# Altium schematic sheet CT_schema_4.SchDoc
size 316 x 185 mm
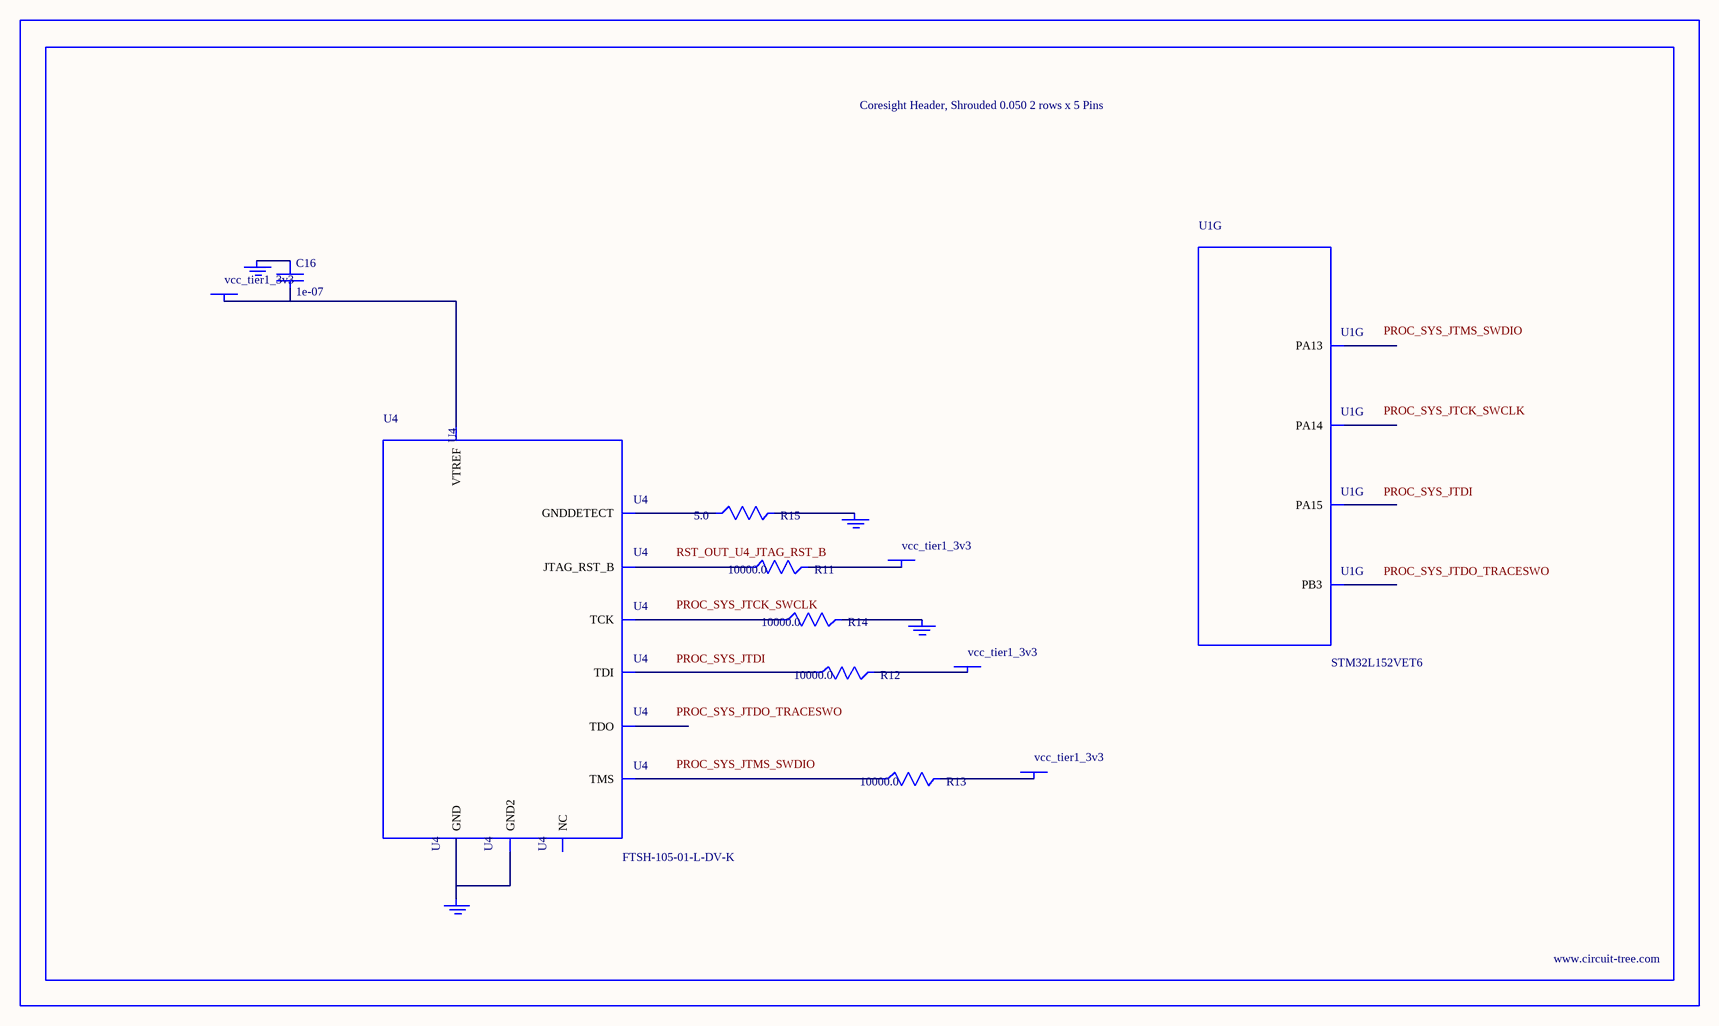
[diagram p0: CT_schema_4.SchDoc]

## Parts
BORDER3  (no value)
C16  1e-07  [C0402]
GND_INSTANCE_3_0  (no value)
GND_INSTANCE_3_1  (no value)
GND_INSTANCE_3_2  (no value)
GND_INSTANCE_3_3  (no value)
POWER_INSTANCE_3_0  vcc_tier1_3v3
POWER_INSTANCE_3_1  vcc_tier1_3v3
POWER_INSTANCE_3_2  vcc_tier1_3v3
POWER_INSTANCE_3_3  vcc_tier1_3v3
R11  10000.0  [R0603]
R12  10000.0  [R0603]
R13  10000.0  [R0603]
R14  10000.0  [R0603]
R15  5.0  [R0603]
U1  STM32L152VET6  [LQFP100]  (part G of 10)
U4  FTSH-105-01-L-DV-K  [SAMTEC_FTSH-105-01-L-DV-K]

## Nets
NetC16_1: C16.1 GND_INSTANCE_3_0.0(GND)
NetC16_2: C16.2 POWER_INSTANCE_3_0.0(PWR) U4.1(VTREF)
NetGND_INSTANCE_3_1_0: GND_INSTANCE_3_1.0(GND) R14.2
NetGND_INSTANCE_3_2_0: GND_INSTANCE_3_2.0(GND) R15.2
NetGND_INSTANCE_3_3_0: GND_INSTANCE_3_3.0(GND) U4.3(GND) U4.5(GND2)
NetPOWER_INSTANCE_3_1_0: POWER_INSTANCE_3_1.0(PWR) R13.2
NetPOWER_INSTANCE_3_2_0: POWER_INSTANCE_3_2.0(PWR) R12.2
NetPOWER_INSTANCE_3_3_0: POWER_INSTANCE_3_3.0(PWR) R11.2
NetR11_1: R11.1 U4.10(JTAG_RST_B)
NetR12_1: R12.1 U4.8(TDI)
NetR13_1: R13.1 U4.2(TMS)
NetR14_1: R14.1 U4.4(TCK)
NetR15_1: R15.1 U4.9(GNDDETECT)

Not connected (* = marked no-connect by the designer): U1 72(PA13) 76(PA14) 77(PA15) 89(PB3); U4 6(TDO) 7(NC)

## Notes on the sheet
- Labels drawn without touching a wire or pin: PROC_SYS_JTCK_SWCLK, PROC_SYS_JTDI, PROC_SYS_JTDO_TRACESWO, PROC_SYS_JTMS_SWDIO, RST_OUT_U4_JTAG_RST_B

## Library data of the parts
BORDER3 = BORDER_PAGE3
C16 = C0402C104K3RACTU
GND_INSTANCE_3_0-GND_INSTANCE_3_3 = GND
POWER_INSTANCE_3_0-POWER_INSTANCE_3_3 = PWR
R11-R14 = RC0603JR-0710KL
R15 = ERJ-3GEYJ5R1V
